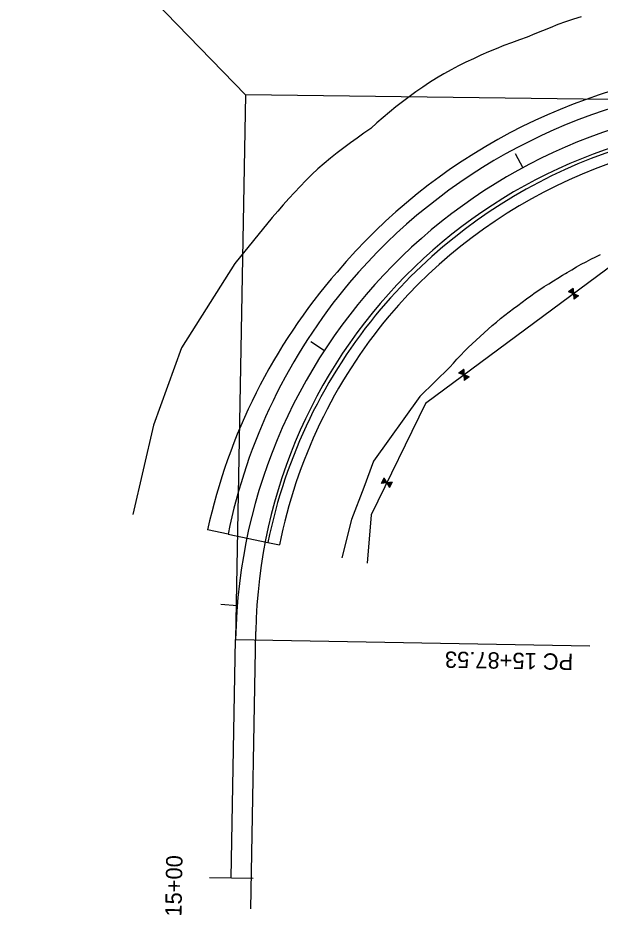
# Model space of a CAD drawing. Extents: x 1311167 to 1314552, y 2087587 to 2090602.
# Drawn here: x 1313625.3 to 1313838.8, y 2089913.1 to 2090242.5 of the extents above; entities that cross this region are included whole.
import ezdxf

# ---------------------------------------------------------------- set-up
doc = ezdxf.new("R2010")
doc.units = 0
for name, color, linetype in [('R_Horz Alg Stationing', 7, 'Continuous'), ('R_Proposed Road', 7, 'Continuous'), ('R_Shld_GR', 7, 'Continuous'), ('R_Shoulder', 7, 'Continuous'), ('S_DROP_INLET', 7, 'Continuous'), ('S_EDGE_CONCRETE', 7, 'Continuous'), ('S_EDGE_PAVEMENT', 7, 'Continuous'), ('S_PAVEMENT_CROWN', 7, 'Continuous')]:
    doc.layers.add(name, color=color, linetype=linetype)

msp = doc.modelspace()

# ---------------------------------------------------------------- linework, layer by layer
at = {"layer": 'R_Horz Alg Stationing'}
msp.add_line((1313710.65, 2089915.39), (1313712.52, 2090017.2), dxfattribs=at)
msp.add_arc((1313903.45, 2090013.7), 190.97, 89.1292, 178.95, dxfattribs=at)
at = {"layer": 'R_Proposed Road'}
msp.add_line((1313703.49, 2089926.82), (1313705.1, 2090014.33), dxfattribs=at)
msp.add_line((1313703.49, 2089926.82), (1313705.1, 2090014.33), dxfattribs=at)
msp.add_arc((1313906.1, 2090010.65), 201.04, 89.25, 178.95, dxfattribs=at)
msp.add_arc((1313906.1, 2090010.65), 201.04, 89.25, 178.95, dxfattribs=at)
at = {"layer": 'R_Shld_GR'}
for points in [[(1313708.76, 2090214.29), (1313625.25, 2090300.46)], [(1313908.73, 2090211.67), (1313708.76, 2090214.29), (1313705.1, 2090014.33)], [(1313705.1, 2090014.33), (1313835.07, 2090011.95)]]:
    msp.add_lwpolyline(points, dxfattribs=at)
at = {"layer": 'R_Shoulder'}
for points in [[(1313807.64, 2090192.78), (1313810.5, 2090187.5)], [(1313732.67, 2090123.73), (1313737.7, 2090120.45)], [(1313699.73, 2090027.27), (1313705.71, 2090026.79)], [(1313695.49, 2089926.97), (1313711.49, 2089926.68)]]:
    msp.add_lwpolyline(points, dxfattribs=at)
at = {"layer": 'S_DROP_INLET'}
for p, q in [((1313829.01, 2090141.6), (1313827.52, 2090142.14)), ((1313829.02, 2090141.72), (1313827.63, 2090142.22)), ((1313828.99, 2090141.85), (1313827.74, 2090142.3)), ((1313829.01, 2090141.96), (1313827.85, 2090142.38)), ((1313828.98, 2090142.09), (1313827.95, 2090142.46)), ((1313828.98, 2090142.21), (1313828.06, 2090142.54)), ((1313828.95, 2090142.34), (1313828.24, 2090142.59)), ((1313828.98, 2090142.44), (1313828.27, 2090142.7)), ((1313828.98, 2090142.56), (1313828.38, 2090142.78)), ((1313828.97, 2090142.68), (1313828.49, 2090142.86)), ((1313828.95, 2090142.81), (1313828.6, 2090142.94)), ((1313828.96, 2090142.92), (1313828.7, 2090143.02)), ((1313828.94, 2090143.05), (1313828.81, 2090143.09)), ((1313828.95, 2090143.16), (1313828.92, 2090143.17)), ((1313828.95, 2090143.2), (1313829.05, 2090141.2)), ((1313829.05, 2090141.2), (1313827.17, 2090141.88)), ((1313829.04, 2090141.24), (1313827.2, 2090141.9)), ((1313829.01, 2090141.37), (1313827.31, 2090141.98)), ((1313829.03, 2090141.48), (1313827.42, 2090142.06)), ((1313829.05, 2090141.2), (1313829.15, 2090139.2)), ((1313830.94, 2090140.52), (1313829.05, 2090141.2)), ((1313829.09, 2090141.17), (1313829.19, 2090139.22)), ((1313829.2, 2090141.11), (1313829.29, 2090139.3)), ((1313829.32, 2090141.09), (1313829.4, 2090139.38)), ((1313829.43, 2090141.04), (1313829.51, 2090139.46)), ((1313829.54, 2090141.01), (1313829.62, 2090139.54)), ((1313829.66, 2090140.95), (1313829.72, 2090139.62)), ((1313829.77, 2090140.93), (1313829.83, 2090139.7)), ((1313829.88, 2090140.87), (1313829.94, 2090139.78)), ((1313830, 2090140.84), (1313830.04, 2090139.86)), ((1313830.11, 2090140.77), (1313830.15, 2090140.01)), ((1313830.22, 2090140.77), (1313830.26, 2090140.02)), ((1313830.33, 2090140.74), (1313830.37, 2090140.1)), ((1313830.45, 2090140.69), (1313830.47, 2090140.18)), ((1313830.56, 2090140.64), (1313830.58, 2090140.26)), ((1313830.68, 2090140.61), (1313830.69, 2090140.34)), ((1313830.79, 2090140.56), (1313830.8, 2090140.42)), ((1313830.9, 2090140.52), (1313830.9, 2090140.5)), ((1313788.84, 2090111.96), (1313787.46, 2090112.45)), ((1313788.82, 2090112.08), (1313787.56, 2090112.53)), ((1313788.83, 2090112.2), (1313787.67, 2090112.61)), ((1313788.8, 2090112.32), (1313787.78, 2090112.69)), ((1313788.81, 2090112.44), (1313787.89, 2090112.77)), ((1313788.78, 2090112.57), (1313788.06, 2090112.83)), ((1313788.81, 2090112.68), (1313788.1, 2090112.93)), ((1313788.81, 2090112.8), (1313788.21, 2090113.01)), ((1313788.79, 2090112.92), (1313788.31, 2090113.09)), ((1313788.78, 2090113.04), (1313788.42, 2090113.17)), ((1313788.78, 2090113.16), (1313788.53, 2090113.25)), ((1313788.77, 2090113.28), (1313788.64, 2090113.33)), ((1313788.77, 2090113.4), (1313788.74, 2090113.41)), ((1313788.78, 2090113.43), (1313788.88, 2090111.43)), ((1313788.88, 2090111.43), (1313786.99, 2090112.11)), ((1313788.87, 2090111.48), (1313787.03, 2090112.14)), ((1313788.84, 2090111.6), (1313787.13, 2090112.22)), ((1313788.85, 2090111.72), (1313787.24, 2090112.3)), ((1313788.84, 2090111.84), (1313787.35, 2090112.38)), ((1313788.88, 2090111.43), (1313788.98, 2090109.43)), ((1313790.76, 2090110.76), (1313788.88, 2090111.43)), ((1313788.91, 2090111.41), (1313789.01, 2090109.46)), ((1313789.03, 2090111.35), (1313789.12, 2090109.54)), ((1313789.14, 2090111.33), (1313789.23, 2090109.62)), ((1313789.25, 2090111.28), (1313789.33, 2090109.7)), ((1313789.37, 2090111.25), (1313789.44, 2090109.78)), ((1313789.48, 2090111.19), (1313789.55, 2090109.86)), ((1313789.59, 2090111.17), (1313789.65, 2090109.94)), ((1313789.71, 2090111.1), (1313789.76, 2090110.01)), ((1313789.82, 2090111.07), (1313789.87, 2090110.09)), ((1313789.94, 2090111.01), (1313789.97, 2090110.25)), ((1313790.05, 2090111), (1313790.08, 2090110.25)), ((1313790.16, 2090110.97), (1313790.19, 2090110.33)), ((1313790.27, 2090110.92), (1313790.3, 2090110.41)), ((1313790.39, 2090110.87), (1313790.41, 2090110.49)), ((1313790.5, 2090110.84), (1313790.51, 2090110.57)), ((1313790.61, 2090110.79), (1313790.62, 2090110.65)), ((1313790.73, 2090110.76), (1313790.73, 2090110.73)), ((1313759.84, 2090073), (1313759.21, 2090072.92)), ((1313759.77, 2090073.11), (1313759.27, 2090073.04)), ((1313759.7, 2090073.21), (1313759.33, 2090073.16)), ((1313759.65, 2090073.32), (1313759.38, 2090073.28)), ((1313759.58, 2090073.42), (1313759.44, 2090073.4)), ((1313759.53, 2090073.52), (1313759.5, 2090073.52)), ((1313759.52, 2090073.56), (1313760.53, 2090071.83)), ((1313760.53, 2090071.83), (1313758.54, 2090071.56)), ((1313760.5, 2090071.86), (1313758.56, 2090071.6)), ((1313760.42, 2090071.96), (1313758.62, 2090071.72)), ((1313760.38, 2090072.07), (1313758.68, 2090071.84)), ((1313760.31, 2090072.17), (1313758.74, 2090071.96)), ((1313760.26, 2090072.28), (1313758.8, 2090072.08)), ((1313760.18, 2090072.38), (1313758.86, 2090072.2)), ((1313760.14, 2090072.48), (1313758.92, 2090072.32)), ((1313760.05, 2090072.58), (1313758.97, 2090072.44)), ((1313760, 2090072.69), (1313759.03, 2090072.56)), ((1313759.89, 2090072.9), (1313759.15, 2090072.8)), ((1313759.92, 2090072.79), (1313759.16, 2090072.69)), ((1313762.51, 2090072.09), (1313760.53, 2090071.83)), ((1313760.53, 2090071.83), (1313761.54, 2090070.1)), ((1313760.57, 2090071.82), (1313761.56, 2090070.14)), ((1313760.7, 2090071.82), (1313761.62, 2090070.26)), ((1313760.81, 2090071.86), (1313761.68, 2090070.38)), ((1313760.94, 2090071.86), (1313761.73, 2090070.5)), ((1313761.05, 2090071.89), (1313761.79, 2090070.62)), ((1313761.18, 2090071.88), (1313761.85, 2090070.74)), ((1313761.29, 2090071.92), (1313761.91, 2090070.86)), ((1313761.42, 2090071.92), (1313761.97, 2090070.97)), ((1313761.53, 2090071.94), (1313762.03, 2090071.1)), ((1313761.67, 2090071.94), (1313762.05, 2090071.28)), ((1313761.77, 2090071.98), (1313762.14, 2090071.34)), ((1313761.88, 2090072.01), (1313762.2, 2090071.45)), ((1313762, 2090072.02), (1313762.26, 2090071.58)), ((1313762.13, 2090072.02), (1313762.32, 2090071.69)), ((1313762.24, 2090072.05), (1313762.38, 2090071.82)), ((1313762.37, 2090072.06), (1313762.44, 2090071.93)), ((1313762.48, 2090072.08), (1313762.5, 2090072.05))]:
    msp.add_line(p, q, dxfattribs=at)
for points in [[(1313949.47, 2090161.13), (1313857.75, 2090162.46), (1313774.8, 2090101), (1313754.78, 2090060.06), (1313753.38, 2090042.36)], [(1313828.95, 2090143.2), (1313827.17, 2090141.88)], [(1313830.94, 2090140.52), (1313829.15, 2090139.2)], [(1313788.78, 2090113.43), (1313786.99, 2090112.11)], [(1313790.76, 2090110.76), (1313788.98, 2090109.43)], [(1313759.52, 2090073.56), (1313758.54, 2090071.56)], [(1313762.51, 2090072.09), (1313761.54, 2090070.1)]]:
    msp.add_lwpolyline(points, dxfattribs=at)
at = {"layer": 'S_EDGE_CONCRETE'}
for points in [[(1313831.93, 2090242.96), (1313829.04, 2090242.03), (1313826.17, 2090241.06), (1313823.32, 2090240.03), (1313820.49, 2090238.92), (1313817.68, 2090237.79), (1313814.88, 2090236.62), (1313812.1, 2090235.41), (1313809.23, 2090234.42), (1313806.37, 2090233.4), (1313803.52, 2090232.32), (1313800.69, 2090231.2), (1313797.88, 2090230.02), (1313795.1, 2090228.79), (1313792.32, 2090227.53), (1313789.56, 2090226.23), (1313786.83, 2090224.88), (1313784.13, 2090223.45), (1313783.09, 2090222.89), (1313781.47, 2090221.96), (1313778.85, 2090220.39), (1313776.28, 2090218.76), (1313773.73, 2090217.07), (1313771.22, 2090215.35), (1313768.74, 2090213.57), (1313766.29, 2090211.75), (1313763.89, 2090209.87), (1313761.53, 2090207.95), (1313759.2, 2090205.98), (1313756.91, 2090203.98), (1313754.69, 2090201.89), (1313752.2, 2090200.14), (1313749.69, 2090198.41), (1313747.2, 2090196.64), (1313744.75, 2090194.83), (1313742.33, 2090192.97), (1313739.94, 2090191.06), (1313737.59, 2090189.1), (1313735.28, 2090187.1), (1313733.05, 2090185.02), (1313730.91, 2090182.84), (1313728.8, 2090180.63), (1313726.71, 2090178.4), (1313724.64, 2090176.15), (1313722.6, 2090173.89), (1313720.57, 2090171.6), (1313718.57, 2090169.29)], [(1313718.57, 2090169.29), (1313704.84, 2090152.36), (1313685.3, 2090121.36), (1313674.94, 2090093.02), (1313667.43, 2090060.21)], [(1313783.67, 2090114.22), (1313784.99, 2090115.72), (1313786.32, 2090117.2), (1313787.68, 2090118.66), (1313789.05, 2090120.11), (1313790.47, 2090121.5), (1313791.91, 2090122.88), (1313793.37, 2090124.24), (1313794.84, 2090125.58), (1313796.32, 2090126.91), (1313797.79, 2090128.25), (1313799.28, 2090129.56), (1313800.79, 2090130.86), (1313802.31, 2090132.15), (1313803.86, 2090133.38), (1313805.43, 2090134.6), (1313807.01, 2090135.8), (1313808.61, 2090136.98), (1313810.19, 2090138.18), (1313811.79, 2090139.35), (1313813.4, 2090140.51), (1313815.03, 2090141.65), (1313816.66, 2090142.77), (1313818.33, 2090143.86), (1313820, 2090144.92), (1313821.69, 2090145.96), (1313823.37, 2090147.01), (1313825.06, 2090148.04), (1313826.11, 2090148.67), (1313826.77, 2090149.07), (1313828.47, 2090150.07), (1313830.19, 2090151.07), (1313831.93, 2090152.04), (1313833.67, 2090152.99), (1313835.42, 2090153.92), (1313837.21, 2090154.8), (1313838.99, 2090155.67)], [(1313783.67, 2090114.22), (1313772.73, 2090103.54), (1313755.74, 2090079.82), (1313752.08, 2090070.15), (1313747.61, 2090058.32), (1313744.11, 2090044.29)]]:
    msp.add_lwpolyline(points, dxfattribs=at)
at = {"layer": 'S_EDGE_PAVEMENT'}
for p, q in [((1313702.31, 2090052.96), (1313694.8, 2090054.52)), ((1313716.93, 2090049.93), (1313721.18, 2090049.05))]:
    msp.add_line(p, q, dxfattribs=at)
for centre, radius, start, end in [((1313906.1, 2090010.65), 214.54, 96.0197, 139.7699), ((1313906.1, 2090010.65), 189.54, 89.25, 139.7699), ((1313904.37, 2090008.63), 214.54, 139.0587, 167.647), ((1313907.01, 2090011.74), 189.54, 140.1983, 168.6472)]:
    msp.add_arc(centre, radius, start, end, dxfattribs=at)
at = {"layer": 'S_PAVEMENT_CROWN'}
msp.add_line((1313702.31, 2090052.96), (1313716.93, 2090049.93), dxfattribs=at)
for centre, radius, start, end in [((1313906.1, 2090010.65), 208.54, 96.0544, 139.7699), ((1313906.1, 2090010.65), 193.54, 89.25, 139.7699), ((1313906.65, 2090011.3), 208.54, 140.0024, 168.4746), ((1313906.55, 2090011.19), 193.54, 139.9783, 168.4533)]:
    msp.add_arc(centre, radius, start, end, dxfattribs=at)

# ---------------------------------------------------------------- texts
at = {"layer": 'R_Shld_GR'}
msp.add_text('PC 15+87.53', height=6, rotation=178.95, dxfattribs=at).set_placement((1313829.02, 2090009.06))
at = {"layer": 'R_Shoulder'}
msp.add_text('15+00', height=6, rotation=88.95, dxfattribs=at).set_placement((1313685.23, 2089912.51))

doc.saveas('drawing.dxf')
